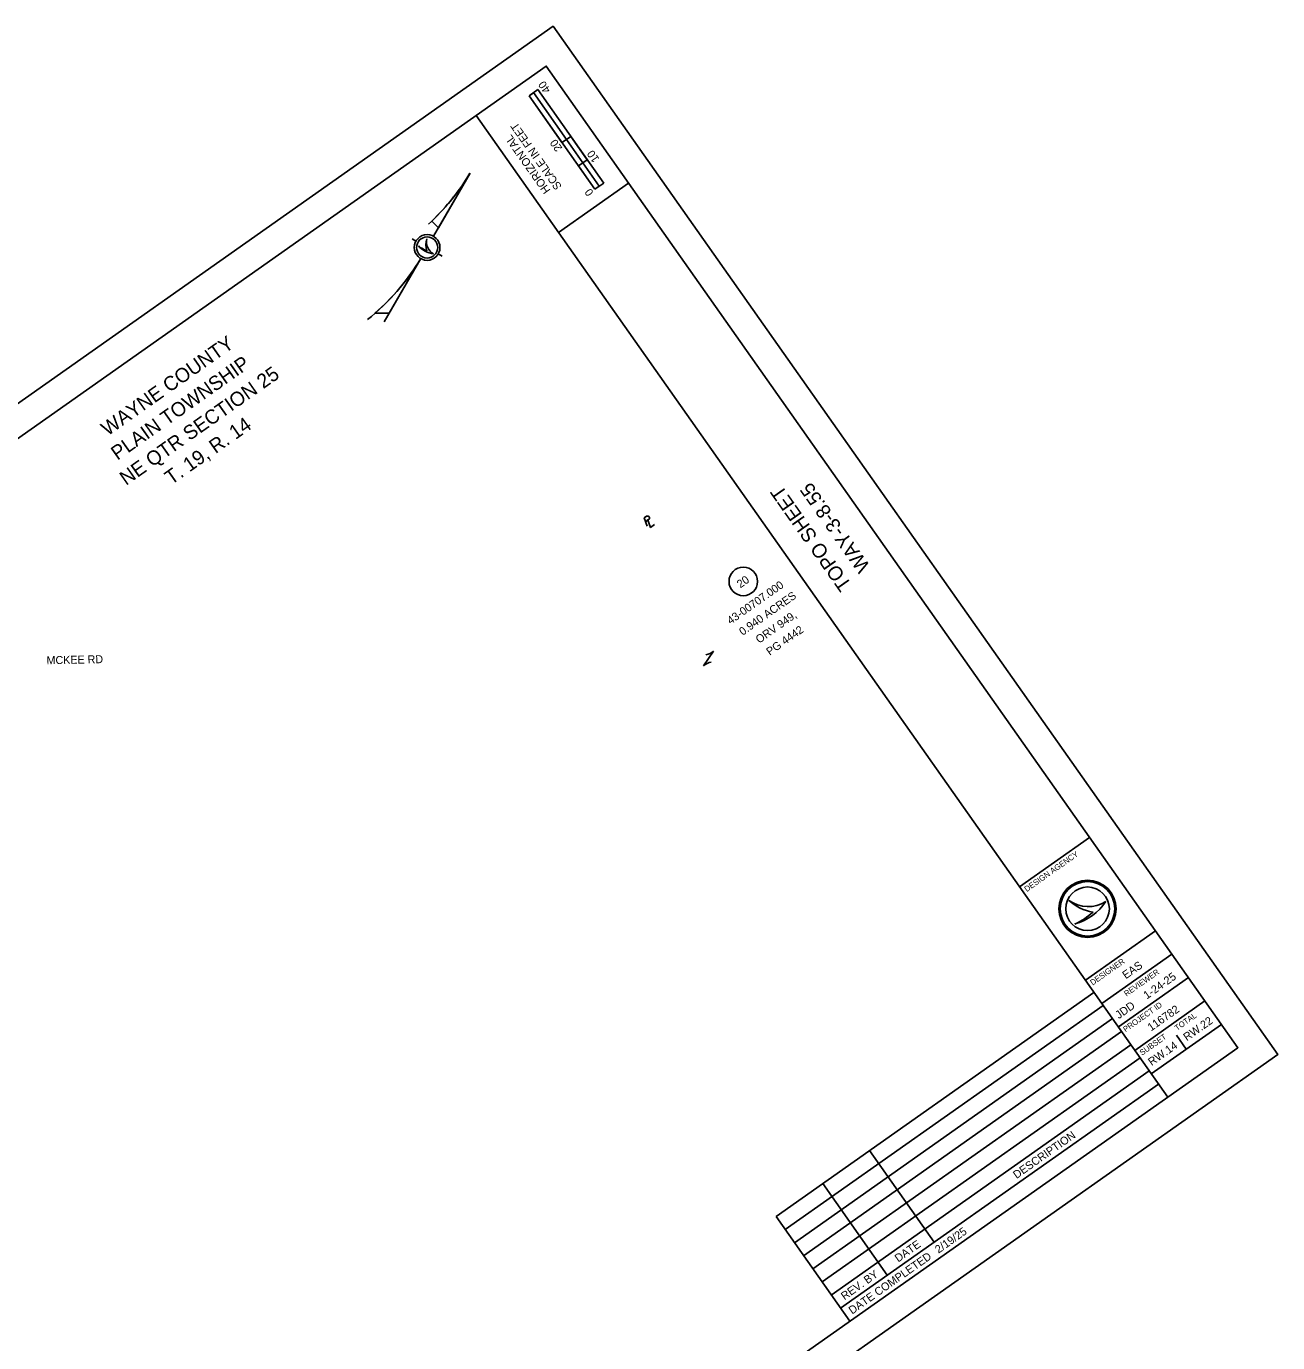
# Model space of a CAD drawing. Extents: x 136960 to 137769, y 475340 to 476091.
# Drawn here: x 137331.7 to 137769.5, y 475631 to 476091.4 of the extents above; entities that cross this region are included whole.
import ezdxf

# ---------------------------------------------------------------- set-up
doc = ezdxf.new("R2010")
doc.units = 0
for name, color, linetype in [('Default', 7, 'Continuous'), ('RD_X_RR_Cells', 7, 'Continuous'), ('SV_P_Mon_Cells_Set', 7, 'Continuous'), ('SV_X_Control_Cells_Found', 7, 'Continuous'), ('SV_X_Mon_Cells_Found', 7, 'Continuous'), ('SV_X_Shot_Marker', 7, 'Continuous')]:
    doc.layers.add(name, color=color, linetype=linetype)

msp = doc.modelspace()

# ---------------------------------------------------------------- linework, layer by layer
at = {"layer": 'Default'}
msp.add_circle((137582.55, 475897.25), 5, dxfattribs=at)
at = {"layer": 'RD_X_RR_Cells'}
msp.add_lwpolyline([(137213.63, 475340.05), (137769.48, 475731.76), (137516.02, 476091.42), (136960.17, 475699.71)], close=True, dxfattribs=at)
at = {"layer": 'SV_P_Mon_Cells_Set'}
for p, q in [((137548.38, 475918.13), (137549.44, 475918.88)), ((137549.39, 475918.08), (137549.39, 475918.08)), ((137568.63, 475867.75), (137572.18, 475872.89)), ((137570.4, 475870.32), (137570.4, 475870.32))]:
    msp.add_line(p, q, dxfattribs=at)
for points in [[(137548.95, 475916.59), (137547.88, 475919.46), (137548.73, 475920.06)], [(137549.06, 475919.02), (137550.11, 475916.15), (137551.54, 475917.16)]]:
    msp.add_lwpolyline(points, dxfattribs=at)
for centre, radius, start, end in [((137549.04, 475919.44), 0.69, 305.6435, 116.5006), ((137568.64, 475876.88), 5.34, 278.867, 311.5095), ((137572.16, 475863.75), 5.34, 98.867, 131.5095)]:
    msp.add_arc(centre, radius, start, end, dxfattribs=at)
at = {"layer": 'SV_X_Control_Cells_Found'}
for p, q in [((137731.02, 475716.89), (137489.08, 476060.2)), ((137517.88, 476019.33), (137542.41, 476036.62)), ((137679.17, 475790.46), (137703.7, 475807.74)), ((137702.22, 475757.76), (137726.74, 475775.04)), ((137707.98, 475749.58), (137732.5, 475766.87)), ((137713.74, 475741.41), (137738.26, 475758.69)), ((137719.5, 475733.24), (137744.02, 475750.52)), ((137725.26, 475725.06), (137749.78, 475742.34))]:
    msp.add_line(p, q, dxfattribs=at)
msp.add_lwpolyline([(136990.45, 475708.82), (137513.6, 476077.49), (137755.54, 475734.17), (137232.39, 475365.5)], close=True, dxfattribs=at)
at = {"layer": 'SV_X_Mon_Cells_Found'}
for p, q in [((137510.67, 476069.3), (137507.6, 476067.14)), ((137507.6, 476067.14), (137509.13, 476068.21)), ((137509.13, 476068.21), (137509.14, 476068.22)), ((137509.14, 476068.22), (137520.66, 476051.88)), ((137510.67, 476069.3), (137533.71, 476036.6)), ((137530.64, 476034.44), (137507.6, 476067.14)), ((137519.12, 476050.79), (137507.6, 476067.14)), ((137520.66, 476051.88), (137519.12, 476050.79)), ((137522.17, 476052.94), (137520.65, 476051.87)), ((137520.65, 476051.87), (137526.41, 476043.69)), ((137527.93, 476044.77), (137522.17, 476052.94)), ((137526.41, 476043.69), (137524.88, 476042.62)), ((137524.88, 476042.62), (137530.64, 476034.44)), ((137526.41, 476043.69), (137527.93, 476044.77)), ((137532.17, 476035.52), (137526.41, 476043.69)), ((137474.2, 476017.97), (137486.95, 476040.05)), ((137533.71, 476036.6), (137530.64, 476034.44)), ((137530.64, 476034.44), (137532.17, 476035.52)), ((137473.59, 476023.29), (137475.92, 476020.94)), ((137466.67, 476017.12), (137468.05, 476016.32)), ((137456.95, 475988.09), (137469.7, 476010.18)), ((137475.85, 476011.82), (137477.23, 476011.02)), ((137458.7, 475991.12), (137453.7, 475991.04)), ((137696.41, 475785.71), (137696.41, 475785.71)), ((137702.96, 475782.75), (137702.96, 475782.75)), ((137709.41, 475785.3), (137709.41, 475785.3)), ((137698.56, 475777.43), (137698.56, 475777.43)), ((137737.52, 475733.7), (137734.06, 475738.61))]:
    msp.add_line(p, q, dxfattribs=at)
for points in [[(137473.57, 476023.31), (137473.59, 476023.29), (137475.92, 476020.95), (137486.95, 476040.05)], [(137453.7, 475991.04), (137458.7, 475991.12), (137469.7, 476010.18)]]:
    msp.add_lwpolyline(points, dxfattribs=at)
for centre, radius in [((137471.95, 476014.07), 4.5), ((137471.95, 476014.07), 3.7), ((137702.96, 475782.75), 10), ((137702.96, 475782.75), 9.54), ((137702.96, 475782.75), 9.54), ((137702.96, 475782.75), 7.64)]:
    msp.add_circle(centre, radius, dxfattribs=at)
for centre, radius, start, end in [((137419.22, 476080.44), 78.85, 312.4153, 329.1947), ((137419.22, 476080.44), 78.85, 313.5754, 329.1947), ((137476.11, 476023.48), 11.43, 230.7277, 247.8734), ((137475.55, 476020.75), 9.05, 222.4874, 261.486), ((137478.65, 476015.03), 7.17, 162.8556, 197.3141), ((137476.8, 476016.18), 5.1, 169.1575, 239.3709), ((137401.97, 476050.56), 78.85, 308.5054, 329.1947), ((137401.97, 476050.56), 78.85, 310.9936, 329.1947), ((137703.21, 475795.1), 11.6, 234.0982, 234.1045), ((137707.3, 475797.31), 15.91, 226.8105, 226.8147), ((137703.21, 475795.1), 11.6, 234.1045, 302.3383), ((137707.3, 475797.31), 15.91, 226.8147, 261.2672), ((137692.76, 475796.85), 20.26, 286.6302, 325.2558), ((137687.99, 475800.44), 25.32, 294.672, 311.8397), ((137687.99, 475800.44), 25.32, 294.6689, 294.672), ((137692.76, 475796.85), 20.26, 286.6253, 286.6302)]:
    msp.add_arc(centre, radius, start, end, dxfattribs=at)
at = {"layer": 'SV_X_Shot_Marker'}
for p, q in [((137593.99, 475675.13), (137705.21, 475753.51)), ((137597.21, 475670.55), (137708.44, 475748.93)), ((137600.44, 475665.97), (137711.66, 475744.35)), ((137603.66, 475661.39), (137714.89, 475739.78)), ((137606.89, 475656.82), (137718.12, 475735.2)), ((137610.12, 475652.24), (137721.34, 475730.62)), ((137613.34, 475647.66), (137724.57, 475726.04)), ((137616.57, 475643.08), (137727.79, 475721.47)), ((137731.02, 475716.89), (137731.02, 475716.89)), ((137626.68, 475698.17), (137649.26, 475666.13)), ((137610.34, 475686.65), (137632.92, 475654.61)), ((137593.99, 475675.13), (137619.79, 475638.51))]:
    msp.add_line(p, q, dxfattribs=at)

# ---------------------------------------------------------------- texts
at = {"layer": 'Default'}
msp.add_text('20', height=2.8, rotation=35.1725, dxfattribs=at).set_placement((137581.53, 475894.82))
at = {"layer": 'SV_X_Mon_Cells_Found'}
for s, height, rotation, p in [('40', 2.8, 125.1725, (137515.3, 476069.2)), ('SCALE IN FEET', 2.8, 125.1725, (137519.19, 476035.44)), ('HORIZONTAL', 2.8, 125.1725, (137515.21, 476034.07)), ('20', 2.8, 125.1725, (137519.38, 476048.83)), ('10', 2.8, 125.1725, (137532.34, 476045)), ('0', 2.8, 125.1725, (137530.33, 476033.28)), ('               WAYNE COUNTY               ', 5, 35.1725, (137337.39, 475931.9)), ('              PLAIN TOWNSHIP              ', 5, 35.1725, (137342.35, 475924.46)), ('             NE QTR SECTION 25            ', 5, 35.1725, (137346.9, 475916.74)), ('               T. 19, R. 14               ', 5, 35.1725, (137359.66, 475914.81)), ('WAY-3-8.55', 5, 125.1725, (137627.11, 475902.53)), ('TOPO SHEET', 5, 125.1725, (137620.65, 475896.08)), ('DESIGN AGENCY', 2, 35.1725, (137681.72, 475788.58)), ('DESIGNER', 2, 35.1725, (137704.76, 475755.88)), ('EAS', 2.8, 35.1725, (137716.36, 475758.06)), ('REVIEWER', 2, 35.1725, (137716.6, 475751.99)), ('1-24-25', 2.8, 35.1725, (137723.72, 475751.01)), ('JDD', 2.8, 35.1725, (137713.9, 475744.1)), ('PROJECT ID', 2, 35.1725, (137716.28, 475739.53)), ('116782', 2.8, 35.1725, (137725.17, 475739.8)), ('TOTAL', 2, 35.1725, (137734.3, 475740)), ('RW.22', 2.8, 35.1725, (137737.69, 475736.39)), ('SUBSET', 2, 35.1725, (137722.04, 475731.36)), ('RW.14', 2.8, 35.1725, (137725.38, 475727.72))]:
    msp.add_text(s, height=height, rotation=rotation, dxfattribs=at).set_placement(p)
at = {"layer": 'SV_X_Shot_Marker'}
for s, rotation, p in [('43-00707.000', 35.1725, (137578.07, 475882.08)), ('0.940 ACRES', 35.1725, (137582.32, 475878.22)), ('ORV 949,', 35.1725, (137588.1, 475875.44)), ('PG 4442', 35.1725, (137591.81, 475871.21)), ('MCKEE RD', 1.1991, (137338.86, 475868.27)), ('DESCRIPTION', 35.1725, (137678.14, 475688.19)), ('2/19/25                             ', 35.1725, (137650.83, 475662.09)), ('DATE', 35.1725, (137636.74, 475659.01)), ('DATE COMPLETED', 35.1725, (137620.62, 475640.8)), ('REV. BY', 35.1725, (137617.95, 475645.77))]:
    msp.add_text(s, height=2.8, rotation=rotation, dxfattribs=at).set_placement(p)

doc.saveas('drawing.dxf')
